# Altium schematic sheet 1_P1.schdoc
size 307 x 218 mm; Symbol: Drawing-Symbol_A4; Device: Drawing-Symbol_A4; Company: 嘉立创EDA; Version: V1.0; Page Size: A4; @Project Name: IP6829Test; @Page Count: 1; @Update Date: 2025-07-26; @Create Date: 2025-07-03; @Schematic Name: Schematic2; @Page No: 1; @Page Name: P1; @Create Time: 17:01:44; @Update Time: 03:01:32; Width: 1170; Height: 825; Region Start: 1; X Region Count: 6; Y Region Count: 4; Blade Width: 10; Title Block Position: 3; @Board Name: IP6826
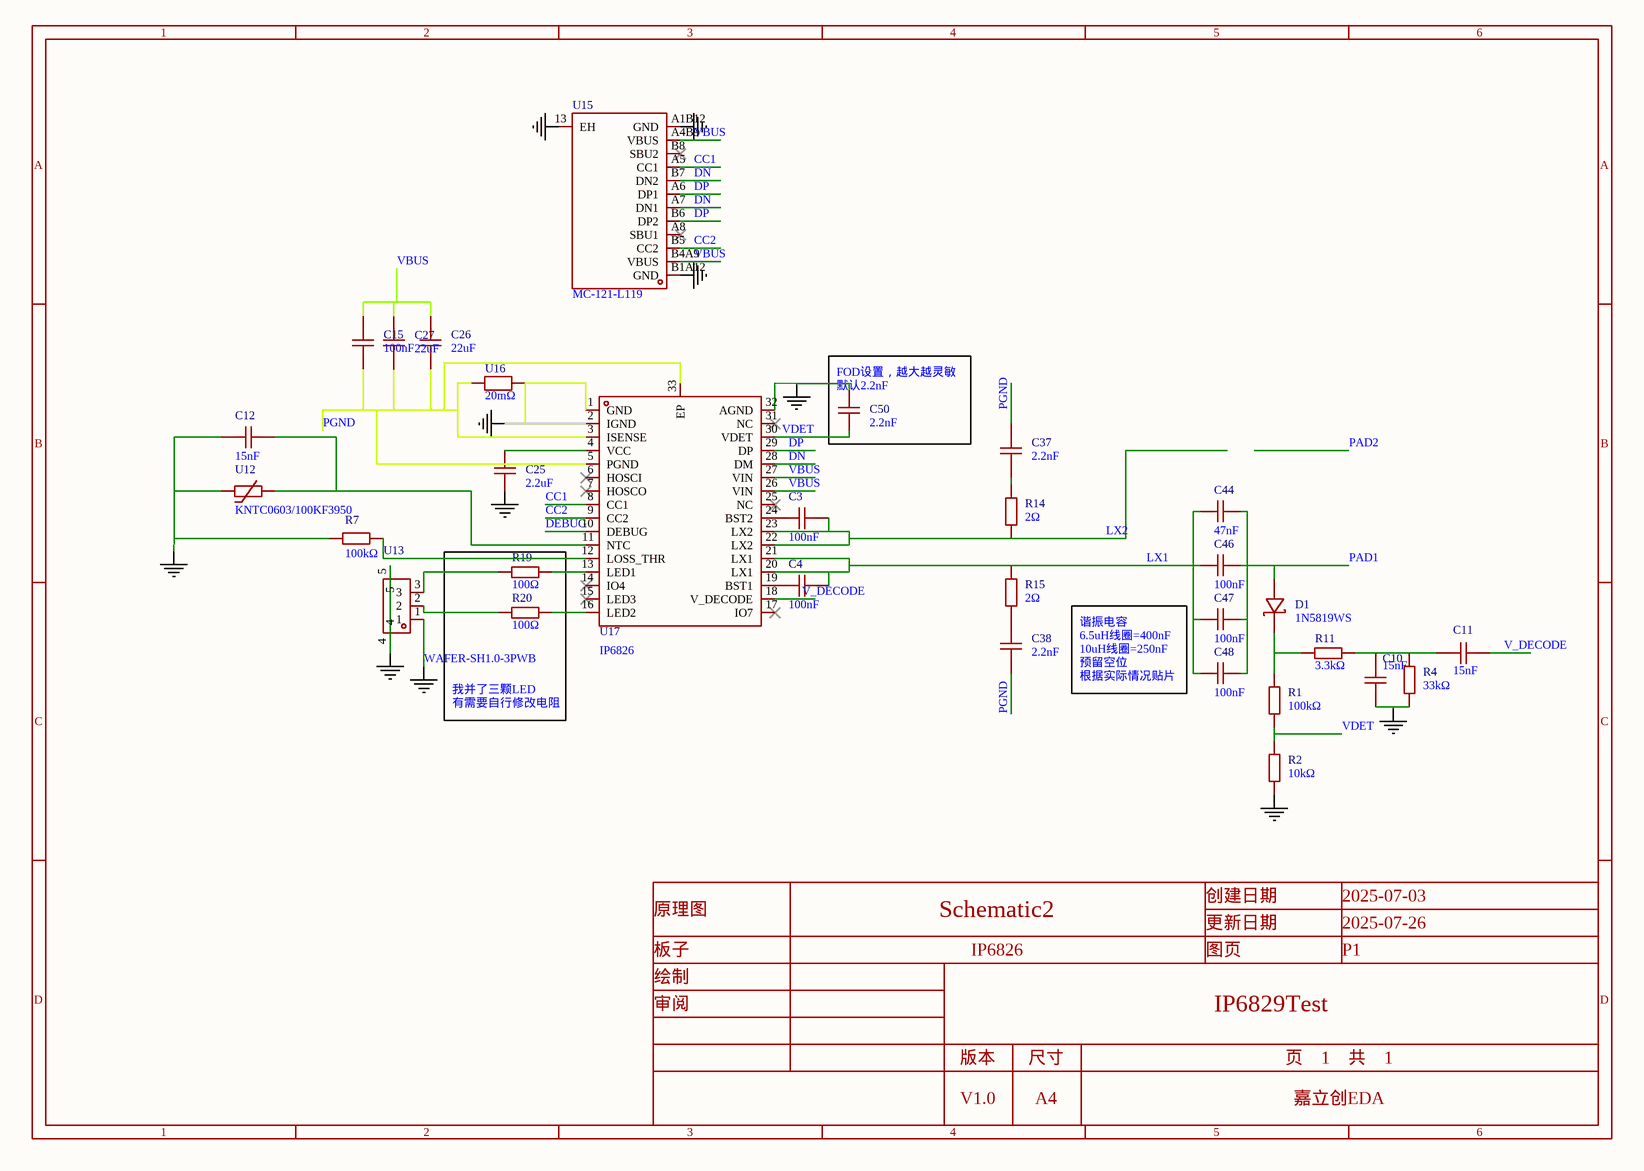
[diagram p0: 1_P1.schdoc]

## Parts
C3  100nF  [C0402]
C4  100nF  [C0402]
C10  15nF  [C0402]
C11  15nF  [C0402]
C12  15nF  [C0402]
C15  100nF  [C0603]
C25  2.2uF  [C0603]
C26  22uF  [C0805]
C27  22uF  [C0805]
C37  2.2nF  [C0402]
C38  2.2nF  [C0402]
C44  47nF  [C1206]
C46  100nF  [C1206]
C47  100nF  [C1206]
C48  100nF  [C1206]
C50  2.2nF  [C0603]
D1  1N5819WS  [SOD-323_L1.8-W1.3-LS2.5-RD]
R1  100kΩ  [R0402]
R2  10kΩ  [R0402]
R4  33kΩ  [R0402]
R7  100kΩ  [R0402]
R11  3.3kΩ  [R0402]
R14  2Ω  [R0402]
R15  2Ω  [R0402]
R19  100Ω  [R0402]
R20  100Ω  [R0402]
U12  KNTC0603/100KF3950  [R0603]
U13  WAFER-SH1.0-3PWB  [CONN-SMD_3P-P1.00_WAFER-SH1.0-3PWB]
U15  MC-121-L119  [USB-C-SMD_HANBO_MC-121-L119]
U16  20mΩ  [R1206]
U17  IP6826  [QFN-32_L5.0-W5.0-P0.50-BL-EP3.8]

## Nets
GND: C10.1 C12.2 C25.1 C50.2 R2.1 R4.1 R7.2 U12.1 U13.1 U13.4 U13.5 U15.13(EH) U15.A1B12(GND) U15.B1A12(GND) U16.2 U17.1(GND) U17.2(IGND) U17.32(AGND)
CC1: U15.A5(CC1) U17.8(CC1)
CC2: U15.B5(CC2) U17.9(CC2)
DEBUG: U17.10(DEBUG)
DN: U15.A7(DN1) U15.B7(DN2) U17.28(DM)
DP: U15.A6(DP1) U15.B6(DP2) U17.29(DP)
LX1: C4.2 C44.1 C46.1 C47.1 C48.1 R15.1 U17.20(LX1) U17.21(LX1)
LX2: C3.2 R14.1 U17.22(LX2) U17.23(LX2)
PAD1: C44.2 C46.2 C47.2 C48.2 D1.2(A)
PGND: C15.1 C26.1 C27.1 C37.2 C38.2 U16.1 U17.3(ISENSE) U17.5(PGND) U17.33(EP)
V_DECODE: C11.1 U17.18(V_DECODE)
VBUS: C15.2 C26.2 C27.2 U15.A4B9(VBUS) U15.B4A9(VBUS) U17.26(VIN) U17.27(VIN)
VDET: C50.1 R1.1 R2.2 U17.30(VDET)
NetC3_1: C3.1 U17.24(BST2)
NetC4_1: C4.1 U17.19(BST1)
NetC10_2: C10.2 C11.2 R4.2 R11.2
NetC12_1: C12.1 U12.2 U17.11(NTC)
NetC25_2: C25.2 U17.4(VCC)
NetC37_1: C37.1 R14.2
NetC38_1: C38.1 R15.2
NetD1_1: D1.1(K) R1.2 R11.1
NetR7_1: R7.1 U17.12(LOSS_THR)
NetR19_1: R19.1 U13.3
NetR19_2: R19.2 U17.13(LED1)
NetR20_1: R20.1 U13.2
NetR20_2: R20.2 U17.16(LED2)

Not connected (* = marked no-connect by the designer): U15 A8(SBU1)* B8(SBU2)*; U17 6(HOSCI)* 7(HOSCO)* 14(IO4)* 15(LED3)* 17(IO7)* 25(NC)* 31(NC)*

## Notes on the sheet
- (near C50) FOD设置，越大越灵敏
  默认2.2nF
- 谐振电容
  6.5uH线圈=400nF
  10uH线圈=250nF
  预留空位
  根据实际情况贴片
- 我并了三颗LED
  有需要自行修改电阻

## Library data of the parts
C3 C4 = CL05B104KB54PNC: Manufacturer: SAMSUNG(三星); Add into BOM: yes; Tolerance: ±10%; Voltage Rated: 50V; Temperature Coefficient: X7R
C10-C12 = CC0402KRX7R9BB153: Manufacturer: YAGEO(国巨); Add into BOM: yes; Tolerance: ±10%; Voltage Rated: 50V; Temperature Coefficient: X7R
C15 = CC0603KRX7R9BB104: Manufacturer: YAGEO(国巨); Add into BOM: yes; Tolerance: ±10%; Voltage Rating: 50V; Temperature Coefficient: X7R
C25 = CL10A225KO8NNNC: Manufacturer: SAMSUNG(三星); Add into BOM: yes; Tolerance: ±10%; Voltage Rated: 16V; Temperature Coefficient: X5R
C26 C27 = CL21A226MAQNNNE: Manufacturer: SAMSUNG(三星); Add into BOM: yes; Tolerance: ±20%; Voltage Rated: 25V; Temperature Coefficient: X5R
C37 C38 = CC0402JRX7R9BB222: Manufacturer: YAGEO(国巨); Add into BOM: yes; Tolerance: ±5%; Voltage Rated: 50V; Temperature Coefficient: X7R
C44 = GRM31M5C1H473JA01L: Manufacturer: muRata(村田); Add into BOM: yes; Tolerance: ±5%; Voltage Rated: 50V; Temperature Coefficient: C0G
C46-C48 = GRM31C5C1H104JA01L: Manufacturer: muRata(村田); Add into BOM: yes; Tolerance: ±5%; Voltage Rated: 50V; Temperature Coefficient: C0G
C50 = 0603B222K500NT: Manufacturer: FH(风华); Add into BOM: yes; Tolerance: ±10%; Voltage Rating: 50V; Temperature Coefficient: X7R
D1 = 1N5819WS_C191023: Manufacturer: Hottech(合科泰); Add into BOM: yes; Forward Voltage (Vf@If): 600mV@1A; Reverse Voltage (Vr): 40V; Rectified Current: 1A
R1 R7 = 0402WGF1003TCE: Manufacturer: UNI-ROYAL(厚声); Add into BOM: yes; Tolerance: ±1%; Power(Watts): 62.5mW; Overload Voltage (Max): 50V; Temperature Coefficient: ±100ppm/℃
R2 = 0402WGF1002TCE: Manufacturer: UNI-ROYAL(厚声); Add into BOM: yes; Tolerance: ±1%; Power(Watts): 62.5mW; Overload Voltage (Max): 50V; Temperature Coefficient: ±100ppm/℃
R4 = 0402WGF3302TCE: Manufacturer: UNI-ROYAL(厚声); Add into BOM: yes; Tolerance: ±1%; Power(Watts): 62.5mW; Overload Voltage (Max): 50V; Temperature Coefficient: ±100ppm/℃
R11 = 0402WGF3301TCE: Manufacturer: UNI-ROYAL(厚声); Add into BOM: yes; Tolerance: ±1%; Power(Watts): 62.5mW; Voltage-Supply(Max): 50V; Temperature Coefficient: ±100ppm/℃
R14 R15 = 0402WGF200KTCE: Manufacturer: UNI-ROYAL(厚声); Add into BOM: yes; Tolerance: ±1%; Power(Watts): 62.5mW; Overload Voltage (Max): 50V; Temperature Coefficient: ±200ppm/℃
R19 R20 = 0402WGF1000TCE: Manufacturer: UNI-ROYAL(厚声); Add into BOM: yes; Tolerance: ±1%; Power(Watts): 62.5mW; Overload Voltage (Max): 50V; Temperature Coefficient: ±200ppm/℃
U12 = KNTC0603/100KF3950: Manufacturer: KUU; Add into BOM: yes; Resistance @ 25℃: 100kΩ; B Constant (25℃/50℃): 3950K; B Constant (25℃/85℃): 4010K; Power(Watts): 100mW; B Constant Tolerance: ±1%; Steady State Current (Max): 100uA
U13 = WAFER-SH1.0-3PWB: Manufacturer: XUNPU(讯普); Add into BOM: yes; Pins Structure: 1x3P; Pitch: 1mm; Reference Series: SH; Number of PINs Per Row: 3; Current Rating: 1A; Voltage Rating: 50V; Plastic Material: LCP; Supplementary Features: 辅助焊脚; Z-Height of the Board: 3.15mm; X-Length of Bottom Edge on Board (Spacing Line): 5.35mm; Y-Width of Bottom Edge on Board: 5.05mm
U15 = MC-121-L119: Manufacturer: HANBO(汉博); Add into BOM: yes; Connector Type: Type-C; Gender: 母; Number of Ports: 1; Number of Contacts: 16P; Current Rating - Power (Max): 5A; Soldering Temperature(Max): 260℃
U16 = FRM121WFR020TM: Manufacturer: FOJAN(富捷); Add into BOM: yes; Tolerance: ±1%; Power(Watts): 1W; Temperature Coefficient: ±50ppm/℃
U17 = IP6826_C2921390: Manufacturer: INJOINIC(英集芯); Symbol: IP6826 QFN32; Add into BOM: yes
